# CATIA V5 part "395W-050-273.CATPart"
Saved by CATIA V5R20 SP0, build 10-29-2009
Part number: 395W-050-273
Bounding box of the stored display mesh (mm): x -11 to 262, y -31.01 to 30, z -30 to 30
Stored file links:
  C:\Users\Raffaele\Desktop\3D X SITO CF\PERNI -STAFFE SOLLEVAMENTO\395W\395W-050-273.CATPart
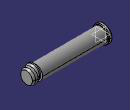
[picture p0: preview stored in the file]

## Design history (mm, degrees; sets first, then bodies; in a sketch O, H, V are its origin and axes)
Body1 (main body)
  Solid1 "ImportedBody": solid without history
